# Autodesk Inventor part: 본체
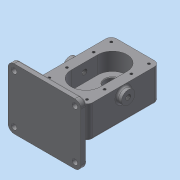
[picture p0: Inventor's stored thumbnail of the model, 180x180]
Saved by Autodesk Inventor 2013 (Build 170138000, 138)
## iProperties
Created: 2020-04
Part Number: 본체
Material: 일반
Document SubType Name: Modeling
Designer: dgall
Density: 1 g/cm^3
Author: dgall
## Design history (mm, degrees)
sketch "스케치1"
  geometry: L1 (-40, 60)-(40, 60); L2 (40, 60)-(40, -60); L3 (40, -60)-(-40, -60); L4 (-40, -60)-(-40, 60); 3 further points
  constraints: 8 end point, 2 midpoint, 2 parallel, 1 horizontal, 1 horizontal alignment, 1 perpendicular, 1 vertical alignment
  dimensions: "d0" = 120 distance of L1.end L2.end; "d2" = 80 distance of L1.start L1.end
extrude "돌출1" new body sketch "스케치1" distance "d3" = 53; taper "d4" = 0 deg
sketch "스케치2"
  geometry: L1 (40, -60)-(40, 60) reference; L2 (-24, 22)-(-24, -22); L3 (24, -22)-(24, 22); A1 r 24 centre (0, -22) between (-24, -22) and (24, -22); A2 r 24 centre (0, 22) between (24, 22) and (-24, 22); 1 further point
  constraints: 4 end point, 4 point on circle, 4 tangent, 2 centre point, 2 parallel, 2 vertical alignment
  dimensions: "d5" = 44 distance of L3.start L3.end; "d7" = 24 radius of A2; "d8" = 22 distance of point (0, 0) A2.centre
extrude "돌출2" cut sketch "스케치2" distance "d9" = 29; taper "d10" = 0 deg
sketch "스케치3"
  geometry: L1 (40, 60)-(-40, 60) reference; C1 r 19 at (0, 22); 1 further point
  constraints: 1 centre point, 1 vertical alignment
  dimensions: "d11" = 38 diameter of C1; "d13" = 38 distance from line of C1.centre L1
sketch "스케치4"
  geometry: L1 (-40, 60)-(40, 60) reference; L2 (40, 60)-(40, -60) reference; L3 (40, -60)-(-40, -60) reference; L4 (-40, -60)-(-40, 60) reference; C1 r 19 at (0, 22) reference; C2 r 12.5 at (0, 22); 1 further point
  constraints: 1 centre point, 1 coincident
  dimensions: "d16" = 25 diameter of C2
extrude "돌출4" cut sketch "스케치4" distance "d18" = 15; taper "d19" = 0 deg
sketch "스케치5"
  geometry: L1 (8, -17)-(46, -17) reference; L2 (38.404, -17)-(38, -16.3); L3 (38, -16.3)-(38, -9.7); L4 (38, -9.7)-(24, -9.7); L5 (24, -9.7)-(24, -17); L6 (9.5, 24)-(34.5, 24) reference; L7 (60, 0)-(60, 53) reference; 1 further point
  constraints: 8 end point, 3 perpendicular, 2 point on line
  dimensions: "d20" = 7.3 distance between parallel lines of L1 L4; "d21" = 0.7 vertical distance of L2.start L2.end; "d22" = 30 deg angle of L3 L2; "d23" = 36 distance from line of L4.end L7; "d24" = 28 diameter of L3 L5
revolve "회전1" sketch "스케치5" stored, may be unused: angle "d25" = 90 deg
sketch "스케치7"
  geometry: L1 (0, 120)-(0, 0) reference; L2 (-53, 0)-(-53, 120) reference; C1 r 11 at (-39, 60); 2 further points
  constraints: 1 centre point, 1 horizontal alignment, 1 midpoint
  dimensions: "d30" = 22 diameter of C1; "d32" = 14 distance from line of C1.centre L2
extrude "돌출6" join sketch "스케치7" distance "d33" = 8; taper "d34" = 0 deg
sketch "스케치8"
  geometry: L1 (60, 0)-(60, 53) reference; L2 (-80, 83)-(-90, 83); L3 (-90, 83)-(-90, -17); L4 (-90, -17)-(-80, -17); L5 (-80, -17)-(-80, 83); L6 (46, 0)-(46, -17) reference; C1 r 4.188 at (0, 39) reference; 1 further point
  constraints: 8 end point, 2 parallel, 1 horizontal, 1 horizontal alignment, 1 perpendicular
  dimensions: "d50" = 100 distance of L2.end L3.end; "d52" = 10 distance of L3.end L4.end; "d53" = 90 distance from line of L3 C1.centre
extrude "돌출7" join sketch "스케치8" stored distance "d54" = 120; taper "d55" = 0 deg
sketch "스케치9"
  geometry: L1 (-40, 60)-(-40, -60) reference; 5 further points
  constraints: 2 horizontal alignment, 2 vertical alignment
  dimensions: "d56" = 22 vertical distance of point (0, 0) point (31, 22); "d57" = 29 distance of point (31, 22) point (31, 51); "d58" = 62 distance of point (-31, 51) point (31, 51); "d59" = 9 distance from line of L1 point (-31, 51)
hole "구멍2" sketch "스케치9" at (-31, 51), (-31, 22), (31, 51), (31, 22) diameter "d60" = 4.134; stored, may be unused: countersink angle "d64" = 90 deg, drill point angle "d66" = 118 deg; dims "d61" = 10, "d62" = 4, "d63" = 2, "d65" = 12
fillet "모깎기1" dims "d67" = 9
fillet "모깎기2" dims "d68" = 10
sketch "스케치10"
  geometry: A1 r 10 centre (0, 90) between (0, 100) and (-10, 90) reference; A2 r 10 centre (0, 10) between (-10, 10) and (0, 0) reference; A3 r 10 centre (100, 90) between (110, 90) and (100, 100) reference; A4 r 10 centre (100, 10) between (100, 0) and (110, 10) reference; 5 further points
  constraints: 4 coincident
hole "구멍3" sketch "스케치10" at (0, 90), (100, 90), (100, 10), (0, 10) diameter "d69" = 9; stored, may be unused: countersink angle "d73" = 90 deg, drill point angle "d75" = 0 deg; dims "d70" = 10, "d71" = 4, "d72" = 2, "d74" = 12
sketch "스케치12"
  geometry: L1 (-51, 53)-(-60, 53) reference; L2 (-60, 53)-(-60, 0) reference; L3 (-60, 0)-(-51, 0) reference; L4 (-51, 0)-(-51, 53) reference; L5 (-80, -7)-(-80, 73) reference; L6 (-80, -7)-(-80, -17) reference; L7 (-80, 83)-(-80, 73) reference; L8 (-60, 0)-(-60, 53) reference; L9 (-60, 11.547)-(-80, 0); L10 (-60, 41.453)-(-80, 53); 1 further point
  constraints: 4 end point, 4 point on line
  dimensions: "d84" = 17 distance of L6.end L9.end; "d85" = 53 distance of L10.end L9.end; "d86" = 60 deg angle of L5 L10; "d87" = 60 deg angle of L5 L9
  node "투영된 루프3"
fillet "모깎기3" dims "d88" = 3
extrude "돌출9" join sketch "스케치12" stored distance "d89" = 48; taper "d90" = 0 deg
fillet "모깎기4" dims "d91" = 3
fillet "모깎기5" dims "d92" = 3
fillet "모깎기6" dims "d93" = 3
fillet "모깎기7" dims "d94" = 3
chamfer "모따기1" distance "d97" = 1; stored, may be unused: second distance "d98" = 2, angle "d99" = 45 deg
sketch "스케치13"
  geometry: L1 (-10, -7)-(-10, -87) reference; L2 (0, -97)-(100, -97) reference; 2 further points
  constraints: 1 other
  dimensions: "d100" = 60 distance from line of L1 point (50, -87); "d101" = 10 distance from line of L2 point (50, -87)
feature "엠보싱1" sketch "스케치13" dims "d0" = 120, "d2" = 80, "d102" = 0.5, "d103" = 0
extrude "돌출10" join sketch "스케치3" distance "d104" = 17; taper "d105" = 0 deg
fillet "모깎기10" dims "d120" = 3
sketch "스케치16"
  geometry: L1 (3, -17)-(41, -17) reference; L2 (36.404, -17)-(36, -16.3); L3 (36, -16.3)-(36, -9.7); L4 (36, -9.7)-(22, -9.7); L5 (22, -9.7)-(22, -17); L6 (36.404, -17)-(22, -17); L7 (60, 53)-(60, 3) reference; 1 further point
  constraints: 10 end point, 3 perpendicular, 1 collinear, 1 midpoint, 1 point on line
  dimensions: "d122" = 30 deg angle of L3 L2; "d123" = 0.7 vertical distance of L2.start L2.end; "d125" = 38 distance from line of L7 L4.end; "d126" = 28 diameter of L3 L5; "d127" = 7.3 distance between parallel lines of L1 L4
revolve "회전3" sketch "스케치16" stored, may be unused: angle "d128" = 90 deg
sketch "스케치17"
  geometry: C1 r 14 at (0, 0) reference; C2 r 8.5 at (0, 0); 1 further point
  constraints: 1 centre point, 1 coincident
  dimensions: "d129" = 17 diameter of C2
extrude "돌출12" cut sketch "스케치17" stored distance "d131" = 17; taper "d132" = 0 deg
fillet "모깎기12" dims "d133" = 0.5
hole "구멍4" diameter "d136" = 8.376; stored, may be unused: countersink angle "d140" = 90 deg, drill point angle "d142" = 118 deg; dims "d134" = 10, "d135" = 10, "d137" = 6, "d138" = 4, "d139" = 2, "d141" = 8
node "솔리드1"
mirror "대칭1"
mirror "대칭2"
mirror "대칭3"
node "투영된 루프1"
